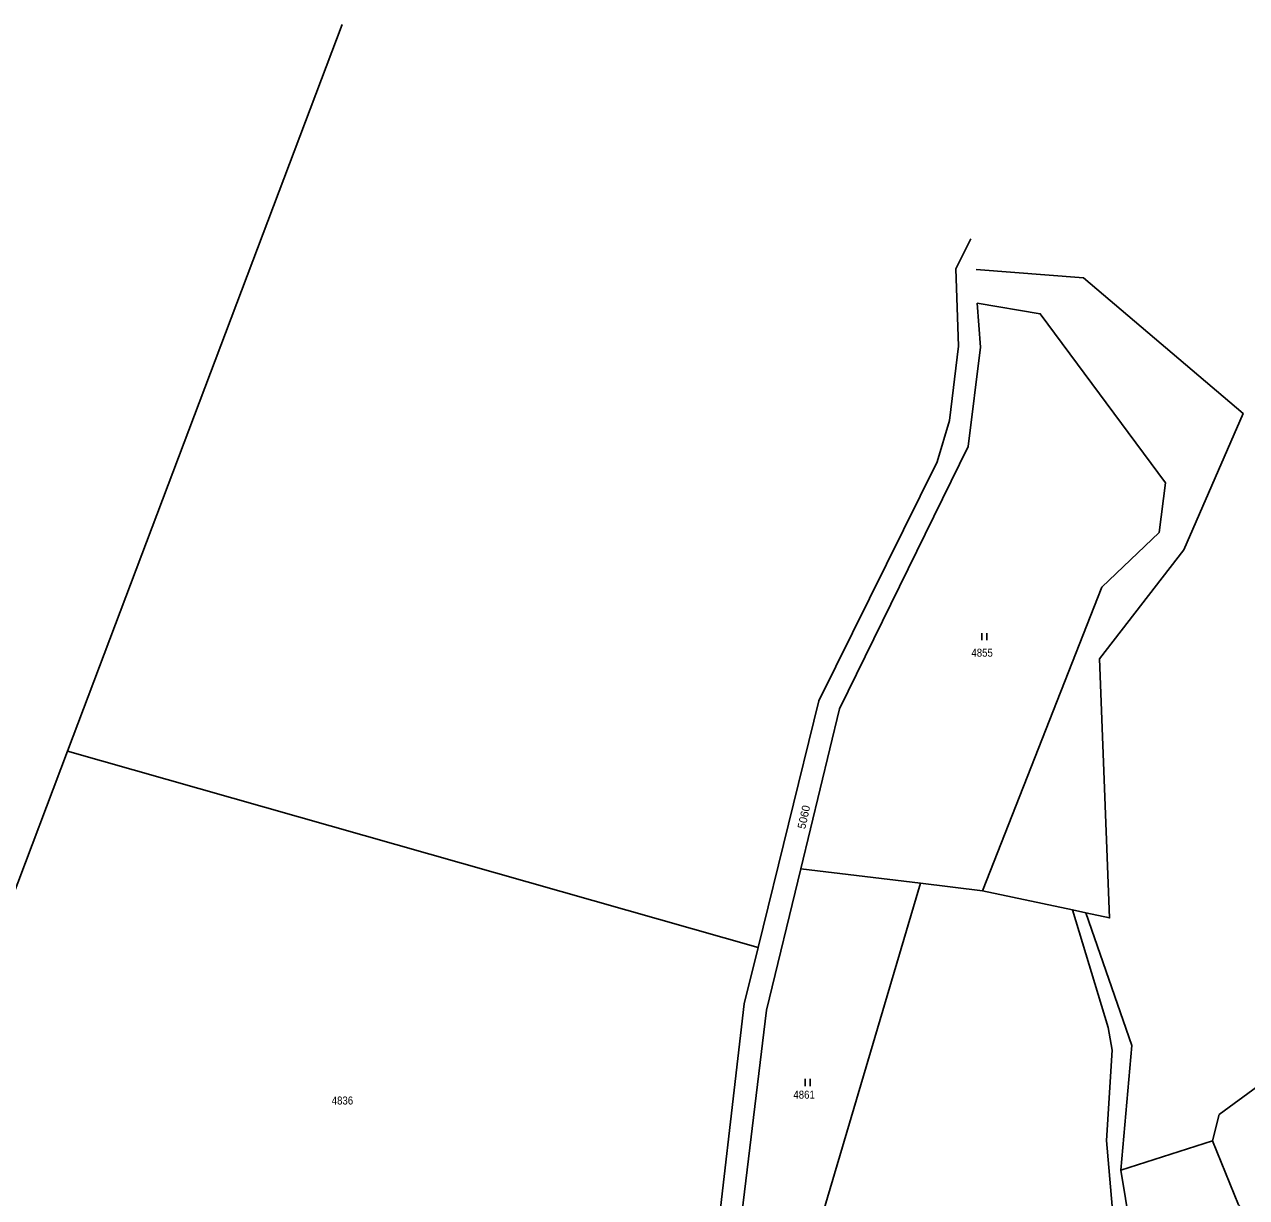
# Model space of a CAD drawing. Extents: x -665688 to -664583, y -1006118 to -1004927.
# Drawn here: x -665191.6 to -664932, y -1005176.4 to -1004927.1 of the extents above; entities that cross this region are included whole.
import ezdxf
from ezdxf.enums import TextEntityAlignment as Align

# ---------------------------------------------------------------- set-up
doc = ezdxf.new("R2010")
doc.units = 0
doc.header["$LTSCALE"] = 0.68
doc.layers.add('1', color=7, linetype='Continuous', lineweight=25)
doc.layers.add('25', color=7, linetype='Continuous', lineweight=25)
doc.layers.add('18', color=7, linetype='Continuous')

msp = doc.modelspace()

# ---------------------------------------------------------------- linework, layer by layer
at = {"layer": '1'}
for p, q in [((-665182.51, -1005081.53), (-665124.17, -1004927.12)), ((-665182.51, -1005081.53), (-665035.77, -1005123.25)), ((-665026.72, -1005106.52), (-665001.26, -1005109.58)), ((-664988.14, -1005111.17), (-665001.26, -1005109.58))]:
    msp.add_line(p, q, dxfattribs=at)
for points in [[(-664990.57, -1004972.7), (-664993.76, -1004979.01), (-664993.18, -1004995.46), (-664995.09, -1005011.27), (-664997.75, -1005020.06), (-665022.88, -1005070.86), (-665035.77, -1005123.25)], [(-664989.49, -1004979.21), (-664966.63, -1004980.97), (-664932.74, -1005009.77), (-664945.36, -1005038.76), (-664963.24, -1005061.92), (-664961.11, -1005116.93), (-664966.14, -1005115.86), (-664968.96, -1005115.26), (-664988.14, -1005111.17)], [(-665026.72, -1005106.52), (-665018.49, -1005072.52), (-664991.18, -1005016.76), (-664988.53, -1004995.66), (-664989.23, -1004986.35)], [(-664988.14, -1005111.17), (-664962.79, -1005046.68), (-664950.57, -1005035.03), (-664949.21, -1005024.52), (-664975.85, -1004988.58), (-664989.23, -1004986.35)], [(-665136.5, -1005215.33), (-665140.44, -1005212.3), (-665152.07, -1005205.93), (-665191.17, -1005188.9), (-665218.73, -1005177.39), (-665216.13, -1005170.52), (-665206.49, -1005145), (-665182.51, -1005081.53)], [(-665049.31, -1005234.5), (-665044.7, -1005224.87), (-665033.98, -1005136.54), (-665026.72, -1005106.52)], [(-665001.26, -1005109.58), (-665031.11, -1005210.37), (-665049.31, -1005234.5)], [(-664968.96, -1005115.26), (-664961.42, -1005140.2), (-664960.58, -1005145.04), (-664961.76, -1005164.25), (-664960.54, -1005178.21), (-664958.55, -1005188.98), (-664953.84, -1005206.17), (-664945.82, -1005230.5), (-664945.31, -1005245.28), (-664948.24, -1005273.87), (-664954.26, -1005296.16), (-665001.62, -1005275.92)], [(-664958.69, -1005170.55), (-664956.42, -1005144.06), (-664966.14, -1005115.86)], [(-665035.77, -1005123.25), (-665038.71, -1005135.19), (-665045.89, -1005196.99), (-665049.31, -1005223.37), (-665052.82, -1005228.77), (-665059.13, -1005232.1), (-665065.99, -1005234.1)], [(-664939.22, -1005164.33), (-664937.81, -1005158.74), (-664929.63, -1005152.7)], [(-664943, -1005227.75), (-664950.93, -1005206.04), (-664955.68, -1005188.99), (-664958.69, -1005170.55), (-664939.22, -1005164.33)], [(-664939.22, -1005164.33), (-664933.7, -1005177.92), (-664925.15, -1005185.97), (-664919.15, -1005193.6), (-664920.98, -1005199.71), (-664918.67, -1005212.71), (-664915.42, -1005217.25), (-664908.82, -1005222.82), (-664898.36, -1005228.3)]]:
    msp.add_lwpolyline(points, dxfattribs=at)
at = {"layer": '25'}
for p, q in [((-664988.247, -1005057.945), (-664988.247, -1005056.445)), ((-664987.213, -1005057.945), (-664987.213, -1005056.445)), ((-665025.777, -1005152.665), (-665025.777, -1005151.165)), ((-665024.743, -1005152.665), (-665024.743, -1005151.165))]:
    msp.add_line(p, q, dxfattribs=at)

# ---------------------------------------------------------------- texts
at = {"layer": '18', "width": 0.9}
for s, p in [('4855', (-664988.1895, -1005061.45)), ('4861', (-665026.0095, -1005155.35)), ('4836', (-665124.0795, -1005156.59))]:
    msp.add_text(s, height=1.7, dxfattribs=at).set_placement(p, align=Align.CENTER)
at = {"layer": '18'}
msp.add_text('5060', height=1.7, rotation=77.401, dxfattribs=at).set_placement((-665025.2377, -1005095.6999), align=Align.CENTER)

doc.saveas('drawing.dxf')
